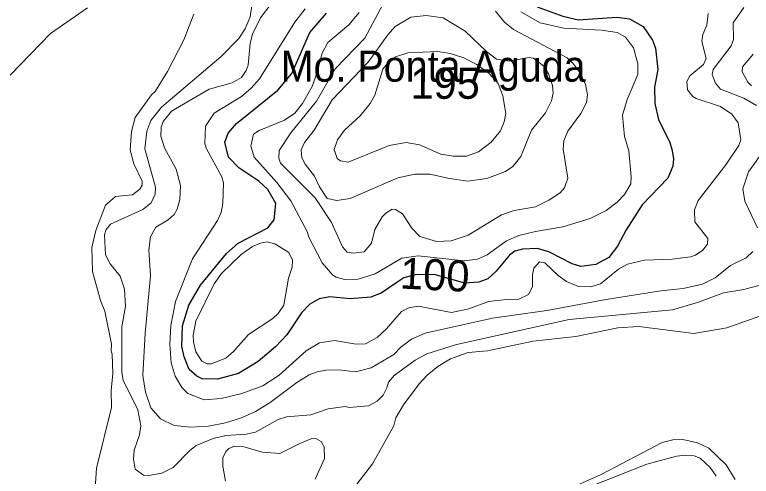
# Model space of a CAD drawing. Extents: x 673.6 to 698.9, y 7012 to 7040.1.
# Drawn here: x 691.831 to 693.729, y 7021.684 to 7022.873 of the extents above; entities that cross this region are included whole.
import ezdxf
from ezdxf.enums import TextEntityAlignment as Align

# ---------------------------------------------------------------- set-up
doc = ezdxf.new("R2010")
doc.units = 0
doc.header["$LTSCALE"] = 0.032
doc.layers.add('1', color=7, linetype='Continuous', lineweight=25)
doc.layers.add('2', color=7, linetype='Continuous', lineweight=13)
for name, color, linetype in [('21', 7, 'Continuous'), ('27', 7, 'Continuous'), ('61', 7, 'Continuous')]:
    doc.layers.add(name, color=color, linetype=linetype)

msp = doc.modelspace()

# ---------------------------------------------------------------- linework, layer by layer
at = {"layer": '1'}
msp.add_lwpolyline([(693.1775, 7022.8938), (693.2432, 7022.87), (693.2839, 7022.8603), (693.3825, 7022.8668), (693.4153, 7022.8626), (693.4504, 7022.8432), (693.4743, 7022.8081), (693.4818, 7022.7867), (693.4877, 7022.7322), (693.4795, 7022.6864), (693.4803, 7022.6447), (693.4895, 7022.6036), (693.5187, 7022.5435), (693.5253, 7022.5237), (693.528, 7022.5017), (693.5264, 7022.4831), (693.5136, 7022.4516), (693.448, 7022.3833), (693.406, 7022.3188), (693.3839, 7022.2765), (693.3621, 7022.2475), (693.3279, 7022.2291), (693.2893, 7022.2243), (693.2675, 7022.2309), (693.2074, 7022.262), (693.1782, 7022.271), (693.1392, 7022.2686), (693.1199, 7022.2637), (693.1058, 7022.2533), (693.0713, 7022.2123), (693.0496, 7022.1929), (693.0271, 7022.184), (692.9905, 7022.1816), (692.9116, 7022.2033), (692.8632, 7022.2028), (692.8334, 7022.1953), (692.8154, 7022.1828), (692.7752, 7022.1557), (692.7485, 7022.1455), (692.6951, 7022.1413), (692.6429, 7022.1461), (692.6151, 7022.1408), (692.5912, 7022.1273), (692.5703, 7022.1047), (692.5322, 7022.0484), (692.5028, 7022.0171), (692.4585, 7021.9791), (692.408, 7021.9483), (692.3532, 7021.9341), (692.3143, 7021.9345), (692.3007, 7021.9418), (692.2806, 7021.9589), (692.2677, 7021.9915), (692.2617, 7022.0184), (692.2632, 7022.071), (692.2798, 7022.1244), (692.31, 7022.1766), (692.3767, 7022.2579), (692.4066, 7022.2844), (692.4834, 7022.3237), (692.4997, 7022.3448), (692.5037, 7022.3868), (692.4834, 7022.4231), (692.4604, 7022.4444), (692.4083, 7022.4787), (692.3823, 7022.5061), (692.3728, 7022.5446), (692.3808, 7022.5677), (692.4022, 7022.5932), (692.5088, 7022.6786), (692.5449, 7022.7219), (692.5918, 7022.8271), (692.6341, 7022.8771)], dxfattribs=at)
at = {"layer": '2'}
for points in [[(693.7505, 7022.1758), (693.7099, 7022.1651), (693.6569, 7022.156), (693.5931, 7022.1324), (693.5259, 7022.1122), (693.2592, 7022.0878), (692.9692, 7022.0235), (692.8932, 7021.9994), (692.8629, 7021.9832), (692.8089, 7021.9436), (692.794, 7021.9265), (692.7895, 7021.9116), (692.7806, 7021.8923), (692.7649, 7021.8774), (692.7426, 7021.8654), (692.6926, 7021.8611), (692.6827, 7021.8633), (692.6387, 7021.8578), (692.5936, 7021.8421), (692.5315, 7021.8364), (692.5102, 7021.83), (692.4517, 7021.7973), (692.4273, 7021.792), (692.3747, 7021.7887), (692.3428, 7021.7808), (692.2988, 7021.7628), (692.2819, 7021.7499), (692.2397, 7021.706), (692.2103, 7021.6917), (692.1765, 7021.6852), (692.1627, 7021.686), (692.1417, 7021.7016), (692.1368, 7021.7276), (692.1391, 7021.7506), (692.1528, 7021.7908), (692.1564, 7021.8133), (692.1481, 7021.8547), (692.1107, 7021.931), (692.1072, 7021.9511), (692.1072, 7022.0685), (692.1161, 7022.1216), (692.1138, 7022.166), (692.1024, 7022.199), (692.0772, 7022.2315), (692.0654, 7022.2546), (692.0628, 7022.3061), (692.0668, 7022.3193), (692.0779, 7022.333), (692.1608, 7022.3709), (692.1826, 7022.3887), (692.1931, 7022.4109), (692.1941, 7022.429), (692.1664, 7022.528), (692.1716, 7022.5729), (692.1821, 7022.6006), (692.2093, 7022.6353), (692.363, 7022.7652), (692.4085, 7022.8124), (692.4251, 7022.8372), (692.4373, 7022.8682), (692.4472, 7022.9319)], [(691.8193, 7022.7179), (691.9229, 7022.825), (692.0186, 7022.8909)], [(692.8082, 7021.9977), (692.7492, 7021.9631), (692.709, 7021.9531), (692.6651, 7021.9579), (692.633, 7021.9571), (692.61, 7021.953), (692.5897, 7021.9453), (692.5577, 7021.9253), (692.489, 7021.8735), (692.4517, 7021.8509), (692.4154, 7021.8345), (692.3742, 7021.8217), (692.3306, 7021.8126), (692.2851, 7021.8101), (692.2423, 7021.8141), (692.2071, 7021.8317), (692.1819, 7021.8598), (692.1677, 7021.9), (692.1614, 7021.9429), (692.1672, 7022.0521), (692.1811, 7022.2006), (692.1769, 7022.2674), (692.1808, 7022.3004), (692.1947, 7022.3253), (692.2265, 7022.3446), (692.2417, 7022.3583), (692.2496, 7022.3725), (692.2566, 7022.3969), (692.2583, 7022.4335), (692.247, 7022.4751), (692.2173, 7022.53), (692.2075, 7022.5604), (692.2081, 7022.5837), (692.2133, 7022.598), (692.2353, 7022.6243), (692.3318, 7022.6815), (692.3912, 7022.6974), (692.4154, 7022.7119), (692.4274, 7022.7293), (692.4325, 7022.7436), (692.4376, 7022.8002), (692.4435, 7022.8232), (692.4645, 7022.8652), (692.4972, 7022.9084)], [(692.7807, 7022.9011), (692.7335, 7022.8129), (692.6568, 7022.7337), (692.6088, 7022.6509), (692.5422, 7022.5687), (692.5121, 7022.5236), (692.5115, 7022.5036), (692.5155, 7022.4908), (692.605, 7022.4017), (692.6472, 7022.3373), (692.6754, 7022.2749), (692.6877, 7022.2613), (692.7042, 7022.2588), (692.7313, 7022.262), (692.7502, 7022.2844), (692.7589, 7022.3196), (692.778, 7022.3519), (692.7873, 7022.3619), (692.8039, 7022.3721), (692.8125, 7022.3712), (692.8302, 7022.3599), (692.8545, 7022.3235), (692.8752, 7022.3018), (692.9175, 7022.2884), (692.9557, 7022.2906), (692.9995, 7022.3047), (693.0853, 7022.3575), (693.1179, 7022.3688), (693.1731, 7022.3784), (693.2072, 7022.3955), (693.236, 7022.4143), (693.2477, 7022.4271), (693.256, 7022.4521), (693.2437, 7022.5267), (693.2454, 7022.5484), (693.2558, 7022.5731), (693.2892, 7022.6188), (693.3039, 7022.6473), (693.3069, 7022.667), (693.3018, 7022.6946), (693.2843, 7022.7277), (693.269, 7022.7485), (693.2545, 7022.7622), (693.1161, 7022.8353), (693.0933, 7022.8545), (693.0698, 7022.8823)], [(693.7094, 7022.8923), (693.6817, 7022.8521), (693.6831, 7022.8094), (693.6771, 7022.7929), (693.6307, 7022.7321), (693.6281, 7022.7188), (693.6369, 7022.6966), (693.6494, 7022.6815), (693.7095, 7022.6581), (693.7421, 7022.6394)], [(692.2927, 7022.8747), (692.2664, 7022.809), (692.2248, 7022.7266), (692.193, 7022.6757), (692.1838, 7022.6671), (692.1417, 7022.6084), (692.1318, 7022.5723), (692.1285, 7022.525), (692.1382, 7022.4891), (692.1593, 7022.4439), (692.1596, 7022.4341), (692.1537, 7022.4236), (692.1345, 7022.4093), (692.0911, 7022.4051), (692.0646, 7022.3823), (692.04, 7022.317), (692.0302, 7022.2731), (692.0314, 7022.2118), (692.0519, 7022.1365), (692.0634, 7022.1095), (692.0807, 7022.0239), (692.0792, 7022.006), (692.0824, 7021.9985), (692.0841, 7021.9485), (692.0792, 7021.9049), (692.0808, 7021.8605), (692.0421, 7021.7046), (692.0381, 7021.6527)], [(692.7345, 7022.025), (692.7112, 7022.0238), (692.6552, 7022.0337), (692.6162, 7022.0274), (692.5824, 7022.0066), (692.512, 7021.9445), (692.47, 7021.9168), (692.4165, 7021.8973), (692.3626, 7021.8842), (692.3188, 7021.8808), (692.2773, 7021.8973), (692.2621, 7021.9116), (692.2443, 7021.9415), (692.2342, 7021.9756), (692.2305, 7022.0245), (692.2337, 7022.0718), (692.2454, 7022.1344), (692.2889, 7022.2442), (692.3538, 7022.343), (692.3626, 7022.3636), (692.3676, 7022.3866), (692.3691, 7022.4399), (692.365, 7022.455), (692.3242, 7022.5296), (692.3209, 7022.5417), (692.3228, 7022.5863), (692.3453, 7022.6192), (692.415, 7022.6627), (692.4402, 7022.6838), (692.4619, 7022.7082), (692.553, 7022.8543), (692.5793, 7022.8888)], [(692.7189, 7022.879), (692.692, 7022.8469), (692.6376, 7022.8013), (692.623, 7022.7741), (692.6096, 7022.7218), (692.5972, 7022.6884), (692.5722, 7022.6444), (692.5528, 7022.6199), (692.5264, 7022.6013), (692.4612, 7022.5747), (692.4459, 7022.5653), (692.4392, 7022.5352), (692.4478, 7022.506), (692.5064, 7022.4412), (692.5422, 7022.3934), (692.5853, 7022.313), (692.588, 7022.3013), (692.6235, 7022.2341), (692.651, 7022.2018), (692.6591, 7022.1966), (692.682, 7022.1906), (692.7156, 7022.1914), (692.7596, 7022.2054), (692.8286, 7022.2456), (692.8706, 7022.252), (692.9893, 7022.239)], [(693.6179, 7022.8766), (693.6144, 7022.8462), (693.6042, 7022.8222), (693.6011, 7022.8039), (693.6124, 7022.7601), (693.6056, 7022.7452), (693.5707, 7022.7162), (693.5631, 7022.7014), (693.564, 7022.6799), (693.5783, 7022.6629), (693.5867, 7022.6576), (693.6493, 7022.6364), (693.6785, 7022.6167), (693.695, 7022.5942), (693.7014, 7022.5508), (693.6964, 7022.5361), (693.6635, 7022.4861), (693.5923, 7022.3946), (693.5825, 7022.37), (693.5837, 7022.3398), (693.6172, 7022.2962), (693.6163, 7022.2818), (693.6037, 7022.2666), (693.5846, 7022.2539), (693.5724, 7022.2496), (693.5253, 7022.2435), (693.4535, 7022.2407), (693.4101, 7022.2307), (693.3868, 7022.2172), (693.3404, 7022.1795), (693.3156, 7022.1715), (693.284, 7022.1727), (693.253, 7022.1855), (693.2309, 7022.2014), (693.1971, 7022.2341), (693.1828, 7022.2364), (693.1689, 7022.2204), (693.1648, 7022.2029), (693.1648, 7022.172), (693.1544, 7022.1517), (693.1301, 7022.1397), (693.0978, 7022.1395), (693.0513, 7022.134), (693.0009, 7022.1148), (692.956, 7022.106), (692.8702, 7022.1223)], [(692.9893, 7022.239), (693.0235, 7022.2429), (693.0485, 7022.2545), (693.0979, 7022.2902), (693.1299, 7022.3046), (693.1732, 7022.3149), (693.2432, 7022.3262), (693.3137, 7022.3477), (693.3546, 7022.3687), (693.3828, 7022.3898), (693.4024, 7022.4102), (693.4184, 7022.4377), (693.4194, 7022.455), (693.4129, 7022.5226), (693.4024, 7022.5592), (693.3972, 7022.6145), (693.4087, 7022.6548), (693.4367, 7022.719), (693.4367, 7022.7469), (693.4252, 7022.7879), (693.4046, 7022.8158), (693.3835, 7022.8276), (693.343, 7022.8339), (693.2458, 7022.839), (693.1849, 7022.8522), (693.1354, 7022.8809)], [(693.7336, 7022.7719), (693.7062, 7022.7387), (693.7055, 7022.7263), (693.7201, 7022.6995), (693.7297, 7022.6898)], [(693.761, 7022.5233), (693.7214, 7022.4682), (693.7071, 7022.4248), (693.7121, 7022.3928), (693.7449, 7022.3242)], [(693.7327, 7022.2627), (693.7158, 7022.2465), (693.675, 7022.2267), (693.6358, 7022.1951), (693.6033, 7022.179), (693.5535, 7022.168), (693.4956, 7022.1618), (693.3549, 7022.1396), (693.2021, 7022.1109)], [(692.7124, 7021.6636), (692.7526, 7021.7158), (692.808, 7021.8134), (692.8127, 7021.8343), (692.8325, 7021.8673), (692.8728, 7021.9215), (692.8938, 7021.9443), (692.9208, 7021.9666), (692.9535, 7021.9859), (692.9992, 7022.0029), (693.0492, 7022.0065), (693.1665, 7022.0318), (693.2763, 7022.0436), (693.3848, 7022.0665), (693.4387, 7022.0697), (693.5805, 7022.0516), (693.6659, 7022.0666), (693.7947, 7022.1115)], [(692.8702, 7022.1223), (692.8462, 7022.1178), (692.8274, 7022.1079), (692.7886, 7022.0634), (692.7652, 7022.0415), (692.7345, 7022.025)], [(693.2021, 7022.1109), (693.0617, 7022.0911), (692.8886, 7022.0523), (692.8534, 7022.0368), (692.8262, 7022.0163), (692.8082, 7021.9977)], [(692.4184, 7021.7607), (692.4684, 7021.7455), (692.5144, 7021.7419), (692.5656, 7021.7681), (692.5969, 7021.7805), (692.6086, 7021.7798), (692.6207, 7021.7729), (692.6281, 7021.7595), (692.6289, 7021.7295), (692.6055, 7021.676)], [(693.6873, 7021.6753), (693.6641, 7021.7128), (693.6196, 7021.756), (693.5905, 7021.7701), (693.5521, 7021.778), (693.5262, 7021.7773), (693.4989, 7021.7705), (693.3423, 7021.6881), (693.2247, 7021.6358)], [(692.3672, 7021.7093), (692.3669, 7021.7308), (692.3749, 7021.7473), (692.3827, 7021.7553), (692.3972, 7021.7608), (692.4184, 7021.7607)], [(693.3123, 7021.6562), (693.4594, 7021.7146), (693.5363, 7021.7352), (693.5597, 7021.7376), (693.582, 7021.7359), (693.5974, 7021.7299), (693.6232, 7021.7065), (693.638, 7021.6835)], [(692.3745, 7021.6708), (692.3672, 7021.7093)]]:
    msp.add_lwpolyline(points, dxfattribs=at)
for points in [[(692.9346, 7022.8652), (692.8915, 7022.8717), (692.8517, 7022.8668), (692.8113, 7022.8428), (692.7921, 7022.8214), (692.7413, 7022.7507), (692.6486, 7022.6542), (692.6028, 7022.5754), (692.5776, 7022.5441), (692.569, 7022.5249), (692.5712, 7022.5043), (692.5793, 7022.4881), (692.6033, 7022.457), (692.616, 7022.4296), (692.6357, 7022.3993), (692.6608, 7022.3943), (692.6952, 7022.4), (692.8184, 7022.4531), (692.8619, 7022.4626), (692.9006, 7022.4626), (692.9514, 7022.4508), (692.9988, 7022.4445), (693.0477, 7022.4508), (693.0958, 7022.469), (693.1142, 7022.4819), (693.1348, 7022.508), (693.1621, 7022.5756), (693.1988, 7022.6205), (693.2139, 7022.6512), (693.218, 7022.671), (693.2166, 7022.6907), (693.2065, 7022.7209), (693.194, 7022.7406), (693.168, 7022.761), (693.155, 7022.7632), (693.1071, 7022.7535), (693.0724, 7022.7591), (693.0469, 7022.7784), (692.9916, 7022.8313)], [(693.0214, 7022.7446), (692.9883, 7022.7623), (692.9532, 7022.7732), (692.921, 7022.7781), (692.8435, 7022.7748), (692.8122, 7022.7649), (692.8, 7022.7579), (692.7797, 7022.7326), (692.7586, 7022.666), (692.7472, 7022.6444), (692.7212, 7022.6124), (692.6809, 7022.5754), (692.6625, 7022.551), (692.6544, 7022.5263), (692.6615, 7022.5024), (692.6708, 7022.4968), (692.6902, 7022.493), (692.7954, 7022.5364), (692.8394, 7022.5439), (692.8738, 7022.5379), (692.9289, 7022.5136), (692.961, 7022.5086), (692.995, 7022.5086), (693.026, 7022.5196), (693.0584, 7022.5444), (693.0823, 7022.5741), (693.092, 7022.5969), (693.0965, 7022.6191), (693.0884, 7022.6644), (693.0769, 7022.6956), (693.0531, 7022.722)], [(692.5375, 7022.2605), (692.5016, 7022.2828), (692.4818, 7022.2875), (692.464, 7022.2843), (692.444, 7022.2759), (692.4147, 7022.2548), (692.3636, 7022.2061), (692.3453, 7022.1795), (692.2975, 7022.0835), (692.2911, 7022.0473), (692.2913, 7022.03), (692.2974, 7022.0046), (692.3133, 7021.9802), (692.3268, 7021.9738), (692.3374, 7021.9737), (692.3747, 7021.9883), (692.3947, 7022.0056), (692.4331, 7022.0488), (692.4965, 7022.0904), (692.5099, 7022.1029), (692.5242, 7022.1245), (692.5361, 7022.1943), (692.546, 7022.223), (692.5467, 7022.2407)]]:
    msp.add_lwpolyline(points, close=True, dxfattribs=at)

# ---------------------------------------------------------------- texts
at = {"layer": '21'}
msp.add_text('195', height=0.08, dxfattribs=at).set_placement((692.8507, 7022.6566))
at = {"layer": '27', "width": 0.95}
msp.add_text('Mo. Ponta Aguda', height=0.08, dxfattribs=at).set_placement((692.9091, 7022.7007), align=Align.CENTER)
at = {"layer": '61'}
msp.add_text('100', height=0.08, rotation=357.118, dxfattribs=at).set_placement((692.9115, 7022.1632), align=Align.CENTER)

doc.saveas('drawing.dxf')
